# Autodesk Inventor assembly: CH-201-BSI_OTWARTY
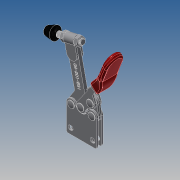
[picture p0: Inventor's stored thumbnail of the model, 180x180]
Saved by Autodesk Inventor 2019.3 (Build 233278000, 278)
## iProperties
Company: ·L?¤¤?
Created: 2010-06
Part Number: CH-201-BSI_OTWARTY
Material: Ogólny
Description: STEP AP203
Document SubType Name: Assembly
Designer: CADENGINEERING4
Sending System: SolidWorks 2005179
Preprocessor: SwSTEP 2.0
Title: CH-201-BSI.STEP
Author: ·L?¥Î?
Revision Number: ANY
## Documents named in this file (9)
- E:\STRONA\Horizontal toggle clamp\CH-201-BSI\CH-201-BSI_OTWARTY.iam
- E:\STRONA\Horizontal toggle clamp\CH-201-BSI\14134-02___.ipt
- E:\STRONA\Horizontal toggle clamp\CH-201-BSI\201-B-06___.ipt
- E:\STRONA\Horizontal toggle clamp\CH-201-BSI\201-B-04___.ipt
- E:\STRONA\Horizontal toggle clamp\CH-201-BSI\BR-142___.ipt
- E:\STRONA\Horizontal toggle clamp\CH-201-BSI\201-B___.iam
- E:\STRONA\Horizontal toggle clamp\CH-201-BSI\201-BSI-02___.ipt
- E:\STRONA\Horizontal toggle clamp\CH-201-BSI\201-BI-01___.ipt
- E:\STRONA\Horizontal toggle clamp\CH-201-BSI\14134___.ipt
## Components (13 placed, 13 different names)
1. 14134-02_??_1 — Zestawiające:4, Zestawiające:6, Równoległe:2
2. 14134-02_??_2 — Zestawiające:5, Zestawiające:7
3. 201-B-06_??_3 — Zestawiające:21, Zestawiające:22, Zestawiające:25
4. 201-B-06_??_4 — Zestawiające:11, Zestawiające:12, Zestawiające:15
5. 201-B-04_??_5 — Zestawiające:8, Zestawiające:9, Zestawiające:10
6. BR-142_??_6 — Zestawiające:2, Równoległe:1, Zestawiające:3, Zestawiające:6, Zestawiające:7
7. 201-B-04_??_7 — Zestawiające:8, Zestawiające:9, Zestawiające:10, Zestawiające:15, Zestawiające:16, Zestawiające:17, Zestawiające:18, Zestawiające:19
8. 201-B_??_8 [sub-assembly] — Zestawiające:18, Zestawiające:19, Zestawiające:20, Zestawiające:21, Zestawiające:22, Przejściowe:1
9. 201-BSI-02_??_9 — Zestawiające:1, Zestawiające:2, Równoległe:1, Zestawiające:23, Zestawiające:24, Zestawiające:25
10. 201-B-06_??_10 — Zestawiające:17, Zestawiające:20
11. 201-BI-01_??_11 — Zestawiające:11, Zestawiające:12, Zestawiające:13, Zestawiające:14, Zestawiające:16, Zestawiające:24, Przejściowe:1
12. 14134_??_12 — Zestawiające:1, Zestawiające:3, Zestawiające:4, Zestawiające:5, Równoległe:2
13. 201-B-06_??_13 — Zestawiające:13, Zestawiające:14, Zestawiające:23
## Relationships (28: Mate 25, Flush 2, Transitional 1)
- Zestawiające:1 [Mate]: 201-BSI-02_??_9 ↔ 14134_??_12
- Zestawiające:2 [Mate]: BR-142_??_6 ↔ 201-BSI-02_??_9
- Równoległe:1 [Flush]: BR-142_??_6 ↔ 201-BSI-02_??_9
- Zestawiające:3 [Mate]: BR-142_??_6 ↔ 14134_??_12
- Zestawiające:4 [Mate]: 14134-02_??_1 ↔ 14134_??_12
- Zestawiające:5 [Mate]: 14134-02_??_2 ↔ 14134_??_12
- Zestawiające:6 [Mate]: 14134-02_??_1 ↔ BR-142_??_6
- Równoległe:2 [Flush]: 14134-02_??_1 ↔ 14134_??_12
- Zestawiające:7 [Mate]: 14134-02_??_2 ↔ BR-142_??_6
- Zestawiające:8 [Mate]: 201-B-04_??_5 ↔ 201-B-04_??_7
- Zestawiające:9 [Mate]: 201-B-04_??_5 ↔ 201-B-04_??_7
- Zestawiające:10 [Mate]: 201-B-04_??_5 ↔ 201-B-04_??_7
- Zestawiające:11 [Mate]: 201-B-06_??_4 ↔ 201-BI-01_??_11
- Zestawiające:12 [Mate]: 201-B-06_??_4 ↔ 201-BI-01_??_11
- Zestawiające:13 [Mate]: 201-BI-01_??_11 ↔ 201-B-06_??_13
- Zestawiające:14 [Mate]: 201-BI-01_??_11 ↔ 201-B-06_??_13
- Zestawiające:15 [Mate]: 201-B-06_??_4 ↔ 201-B-04_??_7
- Zestawiające:16 [Mate]: 201-B-04_??_7 ↔ 201-BI-01_??_11
- Zestawiające:17 [Mate]: 201-B-04_??_7 ↔ 201-B-06_??_10
- Zestawiające:18 [Mate]: 201-B-04_??_7 ↔ 201-B_??_8
- Zestawiające:19 [Mate]: 201-B-04_??_7 ↔ 201-B_??_8
- Zestawiające:20 [Mate]: 201-B_??_8 ↔ 201-B-06_??_10
- Zestawiające:21 [Mate]: 201-B-06_??_3 ↔ 201-B_??_8
- Zestawiające:22 [Mate]: 201-B-06_??_3 ↔ 201-B_??_8
- Zestawiające:23 [Mate]: 201-BSI-02_??_9 ↔ 201-B-06_??_13
- Zestawiające:24 [Mate]: 201-BSI-02_??_9 ↔ 201-BI-01_??_11
- Zestawiające:25 [Mate]: 201-B-06_??_3 ↔ 201-BSI-02_??_9
- Przejściowe:1 [Transitional]: 201-B_??_8 ↔ 201-BI-01_??_11
